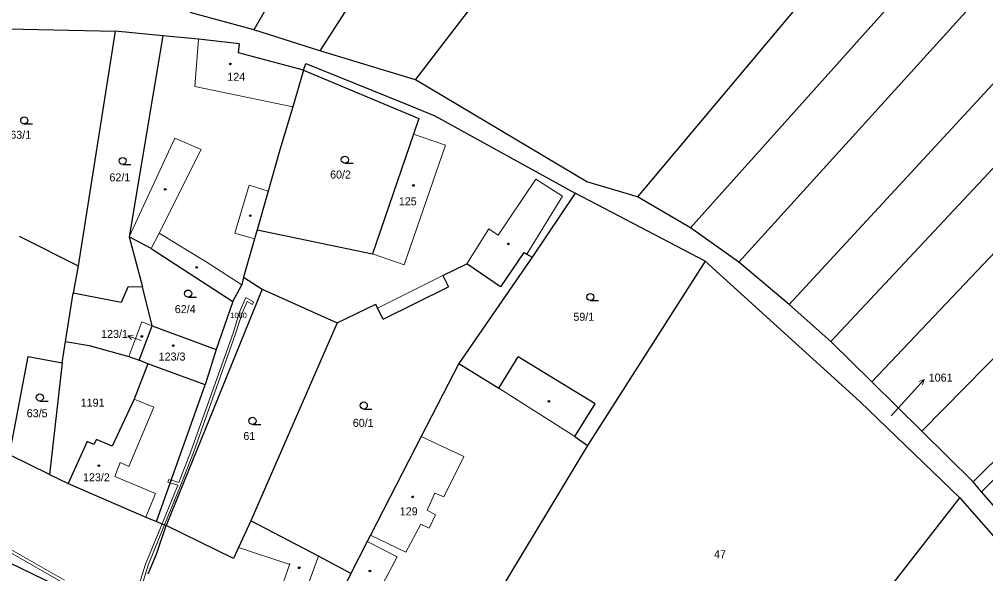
# Model space of a CAD drawing. Extents: x -694609 to -690140, y -1033292 to -1029794.
# Drawn here: x -692814.5 to -692609.2, y -1031203.3 to -1031085.6 of the extents above; entities that cross this region are included whole.
import ezdxf
from ezdxf.enums import TextEntityAlignment as Align

# ---------------------------------------------------------------- set-up
doc = ezdxf.new("R2010")
doc.units = 0
doc.header["$LTSCALE"] = 0.68
for name, color, linetype, lineweight in [('1', 7, 'Continuous', 25), ('13', 7, 'Continuous', 13), ('3', 7, 'Continuous', 25), ('4', 7, 'Continuous', 13), ('5', 7, 'Continuous', 25), ('7', 7, 'Continuous', 13)]:
    doc.layers.add(name, color=color, linetype=linetype, lineweight=lineweight)
doc.layers.add('2', color=7, linetype='Continuous')

msp = doc.modelspace()

# ---------------------------------------------------------------- linework, layer by layer
at = {"layer": '1'}
for p, q in [((-692730.32, -1031098.43), (-692585.59, -1030909.01)), ((-692661.64, -1031137.16), (-692467.96, -1030923.6)), ((-692497.1, -1030934.56), (-692671.89, -1031129.82)), ((-692443.93, -1030942.44), (-692642.1, -1031153.99)), ((-692432.81, -1030951.16), (-692633.39, -1031162.55)), ((-692569.75, -1030988.1), (-692683.18, -1031123.27)), ((-692611.86, -1031183.84), (-692417.77, -1030989.81)), ((-692739.71, -1031044), (-692764.66, -1031087.82)), ((-692731.5, -1031062.57), (-692750.62, -1031092.22)), ((-692764.66, -1031087.82), (-692778.16, -1031084.09)), ((-692784.01, -1031089.07), (-692794.09, -1031088.08)), ((-692750.62, -1031092.22), (-692764.66, -1031087.82)), ((-692784.01, -1031089.07), (-692785.97, -1031100.87)), ((-692776.41, -1031089.76), (-692784.01, -1031089.07)), ((-692767.69, -1031090.79), (-692776.41, -1031089.76)), ((-692767.91, -1031092.65), (-692767.69, -1031090.79)), ((-692754.11, -1031096.38), (-692767.91, -1031092.65)), ((-692730.32, -1031098.43), (-692750.62, -1031092.22)), ((-692622.73, -1031173.04), (-692543.23, -1031092)), ((-692754.11, -1031096.38), (-692753.58, -1031094.95)), ((-692754.11, -1031096.38), (-692756.4, -1031104.13)), ((-692754.11, -1031096.38), (-692729.57, -1031106.65)), ((-692693.9, -1031120.09), (-692730.32, -1031098.43)), ((-692785.97, -1031100.87), (-692791.16, -1031131.75)), ((-692756.4, -1031104.13), (-692759.1, -1031113.28)), ((-692729.57, -1031106.65), (-692730.71, -1031109.97)), ((-692726.21, -1031106.06), (-692696.37, -1031122.51)), ((-692730.71, -1031109.97), (-692739.45, -1031135.38)), ((-692534.7, -1031110.39), (-692610.05, -1031185.96)), ((-692759.1, -1031113.28), (-692761.6, -1031122.04)), ((-692683.18, -1031123.27), (-692693.9, -1031120.09)), ((-692761.6, -1031122.04), (-692763.95, -1031130.25)), ((-692696.37, -1031122.51), (-692705.55, -1031136.05)), ((-692668.77, -1031136.9), (-692696.37, -1031122.51)), ((-692671.89, -1031129.82), (-692683.18, -1031123.27)), ((-692661.64, -1031137.16), (-692671.89, -1031129.82)), ((-692814.49, -1031131.6), (-692801.98, -1031137.94)), ((-692786.45, -1031134.25), (-692791.16, -1031131.75)), ((-692791.16, -1031131.75), (-692788.31, -1031142.36)), ((-692763.95, -1031130.25), (-692764.51, -1031132.22)), ((-692763.95, -1031130.25), (-692739.45, -1031135.38)), ((-692764.51, -1031132.22), (-692766.82, -1031140.33)), ((-692786.45, -1031134.25), (-692769.15, -1031145.52)), ((-692705.55, -1031136.05), (-692721.12, -1031158.64)), ((-692707.31, -1031135.08), (-692712.25, -1031142.36)), ((-692707.31, -1031135.08), (-692706.69, -1031135.42)), ((-692706.69, -1031135.42), (-692705.55, -1031136.05)), ((-692801.98, -1031137.94), (-692803.03, -1031143.71)), ((-692724.52, -1031140), (-692719.39, -1031137.52)), ((-692712.25, -1031142.36), (-692719.39, -1031137.52)), ((-692668.77, -1031136.9), (-692693.76, -1031176.11)), ((-692668.77, -1031136.9), (-692635.89, -1031166.72)), ((-692650.91, -1031146.11), (-692661.64, -1031137.16)), ((-692724.52, -1031140), (-692723.33, -1031142.39)), ((-692769.15, -1031145.52), (-692767.22, -1031141.95)), ((-692766.82, -1031140.33), (-692767.22, -1031141.95)), ((-692766.82, -1031140.33), (-692762.92, -1031142.89)), ((-692804.66, -1031154.01), (-692803.03, -1031143.71)), ((-692792.81, -1031145.69), (-692803.03, -1031143.71)), ((-692791.46, -1031142.47), (-692792.81, -1031145.69)), ((-692788.31, -1031142.36), (-692791.46, -1031142.47)), ((-692786.28, -1031150.64), (-692788.31, -1031142.36)), ((-692762.92, -1031142.89), (-692783.27, -1031193.11)), ((-692762.92, -1031142.89), (-692746.97, -1031150.06)), ((-692737.16, -1031149.28), (-692723.33, -1031142.39)), ((-692769.15, -1031145.52), (-692772.66, -1031155.72)), ((-692746.97, -1031150.06), (-692738.76, -1031146.05)), ((-692738.35, -1031146.89), (-692738.76, -1031146.05)), ((-692642.1, -1031153.99), (-692650.91, -1031146.11)), ((-692737.16, -1031149.28), (-692738.35, -1031146.89)), ((-692746.97, -1031150.06), (-692765.32, -1031192.06)), ((-692789.05, -1031157.98), (-692786.28, -1031150.64)), ((-692786.28, -1031150.64), (-692772.66, -1031155.72)), ((-692805.41, -1031158.54), (-692804.66, -1031154.01)), ((-692804.66, -1031154.01), (-692799.61, -1031154.85)), ((-692633.39, -1031162.55), (-692642.1, -1031153.99)), ((-692799.61, -1031154.85), (-692791.2, -1031157.17)), ((-692772.66, -1031155.72), (-692775, -1031163.19)), ((-692816.55, -1031178.04), (-692812.59, -1031157.2)), ((-692812.59, -1031157.2), (-692805.41, -1031158.54)), ((-692805.41, -1031158.54), (-692808.06, -1031182.27)), ((-692791.2, -1031157.17), (-692789.05, -1031157.98)), ((-692787.15, -1031158.73), (-692790.1, -1031166.21)), ((-692787.15, -1031158.73), (-692789.05, -1031157.98)), ((-692775, -1031163.19), (-692787.15, -1031158.73)), ((-692721.12, -1031158.64), (-692729.1, -1031174.15)), ((-692721.12, -1031158.64), (-692712.58, -1031163.92)), ((-692712.58, -1031163.92), (-692708.48, -1031157.23)), ((-692692.13, -1031167.27), (-692708.48, -1031157.23)), ((-692622.73, -1031173.04), (-692633.39, -1031162.55)), ((-692785.31, -1031192.23), (-692775, -1031163.19)), ((-692790.1, -1031166.21), (-692794.75, -1031176.25)), ((-692635.89, -1031166.72), (-692614.65, -1031187.18)), ((-692696.45, -1031174.15), (-692692.13, -1031167.27)), ((-692611.86, -1031183.84), (-692622.73, -1031173.04)), ((-692798.11, -1031174.81), (-692798.62, -1031175.89)), ((-692794.75, -1031176.25), (-692798.11, -1031174.81)), ((-692729.1, -1031174.15), (-692739.89, -1031195.13)), ((-692696.45, -1031174.15), (-692693.76, -1031176.11)), ((-692800.06, -1031175.26), (-692804.11, -1031184.13)), ((-692798.62, -1031175.89), (-692800.06, -1031175.26)), ((-692693.76, -1031176.11), (-692713.25, -1031208.3)), ((-692808.06, -1031182.27), (-692816.55, -1031178.04)), ((-692808.06, -1031182.27), (-692804.11, -1031184.13)), ((-692804.11, -1031184.13), (-692787.62, -1031191.28)), ((-692610.05, -1031185.96), (-692611.86, -1031183.84)), ((-692680, -1031270.83), (-692614.65, -1031187.18)), ((-692614.65, -1031187.18), (-692595.28, -1031209.44)), ((-692599.63, -1031197.91), (-692610.05, -1031185.96)), ((-692787.62, -1031191.28), (-692785.31, -1031192.23)), ((-692785.32, -1031199.15), (-692783.27, -1031193.11)), ((-692785.31, -1031192.23), (-692783.27, -1031193.11)), ((-692768.99, -1031200.11), (-692783.27, -1031193.11)), ((-692765.32, -1031192.06), (-692767.93, -1031197.78)), ((-692750.94, -1031199.59), (-692765.32, -1031192.06)), ((-692739.89, -1031195.13), (-692740.59, -1031196.49)), ((-692740.59, -1031196.49), (-692744.07, -1031203.26)), ((-692787.11, -1031203.37), (-692785.32, -1031199.15)), ((-692767.93, -1031197.78), (-692768.99, -1031200.11)), ((-692744.07, -1031203.26), (-692750.94, -1031199.59)), ((-692816.48, -1031201.04), (-692793.83, -1031211.92)), ((-692744.07, -1031203.26), (-692745.13, -1031205.46))]:
    msp.add_line(p, q, dxfattribs=at)
for points in [[(-692443.93, -1030942.44), (-692454.85, -1030933.88), (-692650.91, -1031146.11)], [(-692820.24, -1031087.51), (-692794.09, -1031088.08), (-692801.98, -1031137.94)], [(-692753.58, -1031094.95), (-692732.6, -1031103.44), (-692726.21, -1031106.06)]]:
    msp.add_lwpolyline(points, dxfattribs=at)
at = {"layer": '13'}
for points in [[(-692769.08, -1031152.21), (-692778.06, -1031177.34), (-692780.61, -1031183.96), (-692782.2, -1031183.46), (-692782.4, -1031184.03), (-692780.83, -1031184.52), (-692784.16, -1031192.73), (-692783.61, -1031192.97), (-692780.15, -1031184.44), (-692777.5, -1031177.54), (-692768.52, -1031152.39), (-692767.15, -1031147.95), (-692766.09, -1031145.47), (-692764.97, -1031146.1), (-692764.7, -1031145.56), (-692766.37, -1031144.63), (-692767.71, -1031147.75)], [(-692782.72, -1031183.3), (-692782.93, -1031183.86), (-692782.4, -1031184.03), (-692782.2, -1031183.46)]]:
    msp.add_lwpolyline(points, close=True, dxfattribs=at)
for points in [[(-692788.17, -1031204.96), (-692787.12, -1031201.51), (-692783.61, -1031192.97), (-692784.16, -1031192.73), (-692787.68, -1031201.31), (-692789, -1031205.61)], [(-692816.31, -1031198.86), (-692805.19, -1031205.24)], [(-692804.91, -1031204.72), (-692816.26, -1031198.2)]]:
    msp.add_lwpolyline(points, dxfattribs=at)
at = {"layer": '3'}
for p, q in [((-692813.443, -1031107.79), (-692811.693, -1031107.79)), ((-692792.523, -1031116.39), (-692790.773, -1031116.39)), ((-692745.323, -1031116.13), (-692743.573, -1031116.13)), ((-692778.613, -1031144.56), (-692776.863, -1031144.56)), ((-692693.183, -1031145.29), (-692691.433, -1031145.29)), ((-692810.123, -1031166.64), (-692808.373, -1031166.64)), ((-692741.303, -1031168.34), (-692739.553, -1031168.34)), ((-692764.943, -1031171.6), (-692763.193, -1031171.6))]:
    msp.add_line(p, q, dxfattribs=at)
for centre in [(-692813.4429, -1031107.0398), (-692792.5229, -1031115.6398), (-692745.3229, -1031115.3798), (-692778.6129, -1031143.8098), (-692693.1829, -1031144.5398), (-692810.1229, -1031165.8898), (-692741.3029, -1031167.5898), (-692764.9429, -1031170.8498)]:
    msp.add_circle(centre, 0.75, dxfattribs=at)
at = {"layer": '4'}
for p, q in [((-692781.45, -1031110.82), (-692791.16, -1031131.75)), ((-692775.82, -1031113.18), (-692781.45, -1031110.82)), ((-692723.97, -1031112.29), (-692730.71, -1031109.97)), ((-692732.71, -1031137.7), (-692723.97, -1031112.29)), ((-692704.78, -1031119.54), (-692712.72, -1031131.41)), ((-692699.09, -1031123.1), (-692704.78, -1031119.54)), ((-692765.63, -1031120.78), (-692761.6, -1031122.04)), ((-692699.09, -1031123.1), (-692706.69, -1031135.42)), ((-692784.8, -1031130.97), (-692786.45, -1031134.25)), ((-692732.71, -1031137.7), (-692739.45, -1031135.38)), ((-692774.8, -1031137.07), (-692767.22, -1031141.95)), ((-692738.35, -1031146.89), (-692724.52, -1031140)), ((-692788.43, -1031149.83), (-692791.2, -1031157.17)), ((-692786.28, -1031150.64), (-692788.43, -1031149.83)), ((-692712.58, -1031163.92), (-692696.45, -1031174.15)), ((-692785.89, -1031167.93), (-692790.1, -1031166.21)), ((-692791.23, -1031180.55), (-692785.89, -1031167.93)), ((-692729.1, -1031174.15), (-692720.05, -1031178.42)), ((-692724.26, -1031186.99), (-692720.05, -1031178.42)), ((-692793.09, -1031179.71), (-692794.17, -1031182.64)), ((-692793.09, -1031179.71), (-692791.23, -1031180.55)), ((-692727.85, -1031189.84), (-692726.19, -1031186.18)), ((-692726.19, -1031186.18), (-692724.26, -1031186.99)), ((-692726.08, -1031190.79), (-692727.85, -1031189.84)), ((-692727.43, -1031193.63), (-692726.08, -1031190.79)), ((-692732.35, -1031198.78), (-692729.17, -1031192.78)), ((-692729.17, -1031192.78), (-692727.43, -1031193.63)), ((-692739.89, -1031195.13), (-692732.35, -1031198.78)), ((-692734.21, -1031199.77), (-692740.59, -1031196.49)), ((-692767.93, -1031197.78), (-692757.22, -1031201.31)), ((-692757.06, -1031216.3), (-692750.94, -1031199.59)), ((-692738.95, -1031208.71), (-692734.21, -1031199.77)), ((-692757, -1031201.26), (-692761.75, -1031214.73)), ((-692757.22, -1031201.31), (-692757.19, -1031201.19)), ((-692757.19, -1031201.19), (-692757, -1031201.26))]:
    msp.add_line(p, q, dxfattribs=at)
for points in [[(-692756.4, -1031104.13), (-692777.22, -1031099.83), (-692776.41, -1031089.76)], [(-692774.8, -1031137.07), (-692784.8, -1031130.97), (-692775.82, -1031113.18)], [(-692764.51, -1031132.22), (-692768.73, -1031130.98), (-692765.63, -1031120.78)], [(-692719.39, -1031137.52), (-692714.76, -1031130.03), (-692712.72, -1031131.41)], [(-692787.62, -1031191.28), (-692785.52, -1031186.27), (-692794.17, -1031182.64)]]:
    msp.add_lwpolyline(points, dxfattribs=at)
at = {"layer": '5'}
for centre in [(-692769.6368, -1031095.0392), (-692783.4868, -1031121.6792), (-692730.7468, -1031120.8392), (-692765.4068, -1031127.2592), (-692710.5968, -1031133.2492), (-692776.7868, -1031138.2392), (-692788.4568, -1031152.9192), (-692781.7468, -1031154.8492), (-692701.9668, -1031166.6892), (-692797.5868, -1031180.3792), (-692730.8968, -1031187.0092), (-692755.0168, -1031202.0592), (-692740.0068, -1031202.7492)]:
    msp.add_circle(centre, 0.175, dxfattribs=at)
at = {"layer": '7'}
for p, q in [((-692791.4, -1031152.784), (-692790.63, -1031153.597)), ((-692622.272, -1031162.09), (-692623.314, -1031162.499))]:
    msp.add_line(p, q, dxfattribs=at)
for points in [[(-692788.58, -1031153.81), (-692791.4, -1031152.784), (-692790.288, -1031152.656)], [(-692629.25, -1031169.82), (-692624.28, -1031164.32), (-692622.272, -1031162.09), (-692622.57, -1031163.169)]]:
    msp.add_lwpolyline(points, dxfattribs=at)

# ---------------------------------------------------------------- texts
at = {"layer": '2'}
for s, height, p in [('124', 1.7, (-692768.389, -1031098.615)), ('63/1', 1.7, (-692814.179, -1031110.925)), ('60/2', 1.7, (-692746.239, -1031119.375)), ('62/1', 1.7, (-692793.119, -1031119.975)), ('125', 1.7, (-692731.959, -1031125.065)), ('62/4', 1.7, (-692779.239, -1031147.965)), ('1060', 1.14, (-692767.899, -1031149.015)), ('59/1', 1.7, (-692694.559, -1031149.595)), ('123/3', 1.7, (-692782.03, -1031158.045)), ('1191', 1.7, (-692798.91, -1031167.842)), ('63/5', 1.7, (-692810.689, -1031170.085)), ('60/1', 1.7, (-692741.419, -1031172.135)), ('61', 1.7, (-692765.619, -1031174.925)), ('123/2', 1.7, (-692798.1, -1031183.695)), ('129', 1.7, (-692731.749, -1031190.935)), ('47', 1.7, (-692665.619, -1031200.025))]:
    msp.add_text(s, height=height, dxfattribs=at).set_placement(p, align=Align.CENTER)
msp.add_text('123/1', height=1.7, dxfattribs=at).set_placement((-692791.41, -1031153.235), align=Align.RIGHT)
msp.add_text('1061', height=1.7, dxfattribs=at).set_placement((-692621.27, -1031162.515))

doc.saveas('drawing.dxf')
